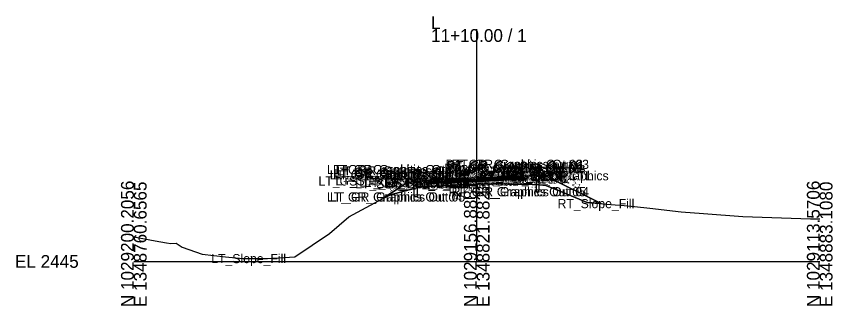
# Model space of a CAD drawing. Extents: x -26 to 1453, y -10 to 4527.
# Drawn here: x 1274.3 to 1452.8, y 490.3 to 553.7 of the extents above; entities that cross this region are included whole.
import ezdxf

# ---------------------------------------------------------------- set-up
doc = ezdxf.new("R2010")
doc.units = 0
for name, color, linetype in [('Default', 7, 'Continuous'), ('Exist Cross Section Cell', 7, 'Continuous'), ('Exist XS Center Line Elevation Label', 7, 'Continuous'), ('Exist XS Ground Line', 7, 'Continuous'), ('Old_Level_63', 7, 'Continuous'), ('Prop CMT Guardrail Graphics', 7, 'Continuous'), ('Prop CMT Pvmt Course 1', 7, 'Continuous'), ('Prop CMT Pvmt Course 2', 7, 'Continuous'), ('Prop CMT Pvmt Course 3', 7, 'Continuous'), ('Prop CMT Pvmt Surface', 7, 'Continuous'), ('Prop CMT Pvmt Surface Overlay', 7, 'Continuous'), ('Prop CMT Pvmt Surface Shoulder', 7, 'Continuous'), ('Prop CMT Shld Paved Course 1', 7, 'Continuous'), ('Prop CMT Shld Paved Course 2', 7, 'Continuous'), ('Prop CMT Shld Paved Course 3', 7, 'Continuous'), ('Prop CMT Slope Grass', 7, 'Continuous'), ('Prop CMT Subgrade Earthwork', 7, 'Continuous'), ('Prop XS Earthwork Shape', 7, 'Continuous'), ('Prop XS EOT Tick Mark', 7, 'Continuous'), ('Prop XS SE Text', 7, 'Continuous'), ('Prop XS Side Slope Text', 7, 'Continuous')]:
    doc.layers.add(name, color=color, linetype=linetype)

msp = doc.modelspace()

# ---------------------------------------------------------------- linework, layer by layer
at = {"layer": 'Exist Cross Section Cell'}
for p, q in [((1375, 500), (1375, 550.87)), ((1300, 500), (1375, 500)), ((1375, 500), (1450, 500))]:
    msp.add_line(p, q, dxfattribs=at)
at = {"layer": 'Exist XS Ground Line'}
msp.add_lwpolyline([(1300, 505.37), (1304.69, 504.48), (1307.15, 504.08), (1308.11, 503.92), (1309.26, 503.98), (1310.55, 503.15), (1314.96, 501.58), (1320.06, 501), (1323.81, 500.63), (1329.25, 500.62), (1335.24, 500.97), (1342.79, 506.1), (1347.02, 509.73), (1353.64, 513.34), (1356.17, 514.56), (1362.42, 516.23), (1367.27, 516.58), (1372.19, 516.81), (1375, 516.91), (1376.28, 516.96), (1381.72, 516.93), (1385.7, 516.95), (1389.88, 516.69), (1392.14, 515.8), (1399.17, 512.92), (1404.35, 512.47), (1407.24, 512.25), (1409.51, 512.01), (1412.85, 511.66), (1419.69, 510.86), (1424.57, 510.48), (1433.18, 509.87), (1447.99, 509.35), (1450, 509.29)], dxfattribs=at)
at = {"layer": 'Prop CMT Guardrail Graphics'}
for points in [[(1361.33, 514.12), (1361.33, 520.12)], [(1361.33, 520.12), (1362.66, 520.12), (1362.93, 519.83)], [(1362.93, 519.83), (1362.66, 519.53)], [(1362.66, 519.53), (1362.93, 519.24)], [(1388.66, 521.26), (1387.32, 521.26), (1387.05, 520.97)], [(1387.05, 520.97), (1387.32, 520.68)], [(1387.32, 520.68), (1387.05, 520.39)], [(1387.05, 520.39), (1387.32, 520.1), (1387.99, 520.1)], [(1387.99, 520.1), (1387.99, 515.26)], [(1388.66, 515.26), (1388.66, 521.26)], [(1362.93, 519.24), (1362.66, 518.95), (1361.99, 518.95)], [(1361.99, 518.95), (1361.99, 514.12)], [(1387.99, 515.26), (1388.66, 515.26)], [(1361.99, 514.12), (1361.33, 514.12)]]:
    msp.add_lwpolyline(points, dxfattribs=at)
at = {"layer": 'Prop CMT Pvmt Course 1'}
for points in [[(1375, 518.28), (1365, 517.78)], [(1365, 517.53), (1375, 518.03)], [(1365, 517.78), (1365, 517.53)], [(1375, 518.28), (1385, 518.78)], [(1385, 518.53), (1375, 518.03)], [(1375, 518.16), (1375, 518.28)], [(1375, 518.16), (1375, 518.28)], [(1375, 518.03), (1375, 518.16), (1375, 518.16)], [(1375, 518.03), (1375, 518.16), (1375, 518.16)], [(1385, 518.78), (1385, 518.53)]]:
    msp.add_lwpolyline(points, dxfattribs=at)
at = {"layer": 'Prop CMT Pvmt Course 2'}
for points in [[(1375, 518.03), (1365, 517.53)], [(1365, 517.28), (1375, 517.78)], [(1375, 518.03), (1385, 518.53)], [(1385, 518.28), (1375, 517.78)], [(1375, 517.78), (1375, 518.03)], [(1375, 517.78), (1375, 518.03)], [(1385, 518.53), (1385, 518.28)], [(1365, 517.53), (1365, 517.28)]]:
    msp.add_lwpolyline(points, dxfattribs=at)
at = {"layer": 'Prop CMT Pvmt Course 3'}
for points in [[(1375, 517.78), (1365, 517.28)], [(1375, 517.78), (1385, 518.28)], [(1385, 518.03), (1375, 517.53)], [(1375, 517.53), (1375, 517.78)], [(1375, 517.53), (1375, 517.78)], [(1385, 518.28), (1385, 518.03)], [(1365, 517.03), (1375, 517.53)], [(1365, 517.28), (1365, 517.03)]]:
    msp.add_lwpolyline(points, dxfattribs=at)
at = {"layer": 'Prop CMT Pvmt Surface'}
for points in [[(1375, 518.28), (1365, 517.78)], [(1375, 518.28), (1385, 518.78)]]:
    msp.add_lwpolyline(points, dxfattribs=at)
at = {"layer": 'Prop CMT Pvmt Surface Overlay'}
for points in [[(1375, 518.28), (1365, 517.78)], [(1375, 518.28), (1385, 518.78)]]:
    msp.add_lwpolyline(points, dxfattribs=at)
at = {"layer": 'Prop CMT Pvmt Surface Shoulder'}
for points in [[(1365, 517.78), (1365, 517.78)], [(1385, 518.78), (1385, 518.78)]]:
    msp.add_lwpolyline(points, dxfattribs=at)
at = {"layer": 'Prop CMT Shld Paved Course 1'}
for points in [[(1365, 517.78), (1365, 517.78), (1364.74, 517.52)], [(1365, 517.53), (1365, 517.78)], [(1385, 518.78), (1385, 518.78), (1385.24, 518.54)], [(1385, 518.53), (1385, 518.78)], [(1385.24, 518.54), (1385, 518.53)], [(1364.74, 517.52), (1365, 517.53)]]:
    msp.add_lwpolyline(points, dxfattribs=at)
at = {"layer": 'Prop CMT Shld Paved Course 2'}
for points in [[(1385, 518.53), (1385.24, 518.54), (1385.48, 518.31)], [(1385, 518.28), (1385, 518.53)], [(1385.48, 518.31), (1385, 518.28)], [(1365, 517.53), (1364.74, 517.52), (1364.47, 517.26)], [(1364.47, 517.26), (1365, 517.28)], [(1365, 517.28), (1365, 517.53)]]:
    msp.add_lwpolyline(points, dxfattribs=at)
at = {"layer": 'Prop CMT Shld Paved Course 3'}
for points in [[(1385, 518.28), (1385.48, 518.31)], [(1385, 518.03), (1385, 518.28)], [(1385.72, 518.07), (1385, 518.03)], [(1385.48, 518.31), (1385.48, 518.31)], [(1385.48, 518.31), (1385.72, 518.07)], [(1364.47, 517.26), (1364.21, 516.99)], [(1364.21, 516.99), (1365, 517.03)], [(1365, 517.28), (1364.47, 517.26)], [(1364.47, 517.26), (1364.47, 517.26)], [(1365, 517.03), (1365, 517.28)]]:
    msp.add_lwpolyline(points, dxfattribs=at)
at = {"layer": 'Prop CMT Slope Grass'}
for points in [[(1365, 517.78), (1362.93, 517.62)], [(1385, 518.78), (1387.05, 518.76)], [(1387.05, 518.76), (1390.05, 518.73)], [(1390.05, 518.73), (1402.2, 512.66)], [(1359.93, 517.38), (1354.49, 513.75)], [(1362.93, 517.62), (1359.93, 517.38)]]:
    msp.add_lwpolyline(points, dxfattribs=at)
at = {"layer": 'Prop CMT Subgrade Earthwork'}
for points in [[(1375, 517.53), (1385, 518.03)], [(1385, 518.03), (1385.72, 518.07)], [(1385.72, 518.07), (1386.42, 518.77)], [(1364.21, 516.99), (1363.54, 517.67)], [(1365, 517.03), (1364.21, 516.99)], [(1375, 517.53), (1365, 517.03)]]:
    msp.add_lwpolyline(points, dxfattribs=at)
at = {"layer": 'Prop XS Earthwork Shape'}
for points in [[(1390.05, 518.73), (1402.2, 512.66), (1399.17, 512.92), (1392.14, 515.8), (1389.88, 516.69), (1385.7, 516.95), (1381.72, 516.93), (1376.28, 516.96), (1375, 516.91), (1372.19, 516.81), (1367.27, 516.58), (1362.42, 516.23), (1356.17, 514.56), (1354.49, 513.75), (1359.93, 517.38), (1362.93, 517.62), (1363.54, 517.67), (1364.21, 516.99), (1365, 517.03), (1375, 517.53), (1385, 518.03), (1385.72, 518.07), (1386.42, 518.77), (1387.05, 518.76)], [(1365, 517.03), (1364.21, 516.99), (1363.54, 517.67), (1362.93, 517.62), (1359.93, 517.38), (1354.49, 513.75), (1356.17, 514.56), (1362.42, 516.23), (1367.27, 516.58), (1372.19, 516.81), (1375, 516.91), (1376.28, 516.96), (1381.72, 516.93), (1385.7, 516.95), (1389.88, 516.69), (1392.14, 515.8), (1399.17, 512.92), (1402.2, 512.66), (1390.05, 518.73), (1387.05, 518.76), (1386.42, 518.77), (1385.72, 518.07), (1385, 518.03), (1375, 517.53)]]:
    msp.add_lwpolyline(points, close=True, dxfattribs=at)
at = {"layer": 'Prop XS EOT Tick Mark'}
for points in [[(1385, 518.78), (1385, 519.78)], [(1365, 517.78), (1365, 518.78)]]:
    msp.add_lwpolyline(points, dxfattribs=at)

# ---------------------------------------------------------------- texts
at = {"layer": 'Default'}
msp.add_text('-', height=0.0001, dxfattribs=at).set_placement((1300, 500))
at = {"layer": 'Exist Cross Section Cell'}
for s, p in [('L', (1365, 550.87)), ('11+10.00 / 1', (1365, 548.07)), ('EL 2445', (1274, 498.6))]:
    msp.add_text(s, height=2.8, dxfattribs=at).set_placement(p)
for s, p in [('N 1029200.2056', (1300, 490)), ('E 1348760.6565', (1302.8, 490)), ('N 1029156.8881', (1375, 490)), ('E 1348821.8823', (1377.8, 490)), ('N 1029113.5706', (1450, 490)), ('E 1348883.1080', (1452.8, 490))]:
    msp.add_text(s, height=2.8, rotation=90, dxfattribs=at).set_placement(p)
at = {"layer": 'Exist XS Center Line Elevation Label'}
msp.add_text('2461.91', height=1.23, dxfattribs=at).set_placement((1372.25, 515.18))
at = {"layer": 'Old_Level_63'}
for s, p in [('RT_GR_Graphics Out 08', (1367.9, 519.39)), ('RT_GR_Graphics Out 02', (1368.17, 520.26)), ('RT_GR_Graphics Out 09', (1368.17, 519.68)), ('RT_GR_Graphics Out 01', (1368.47, 519.97)), ('RT_GR_Graphics Out 03', (1369.51, 520.26)), ('LT_GR_Graphics Out 03', (1342.22, 519.12)), ('LT_GR_Graphics Out 06', (1342.84, 517.95)), ('LT_GR_Graphics Out 02', (1343.56, 519.12)), ('LT_GR_Graphics Out 09', (1343.56, 518.53)), ('LT_GR_Graphics Out 07', (1343.56, 517.95)), ('LT_GR_Graphics Out 08', (1343.83, 518.24)), ('LT_GR_Graphics Out 01', (1344.4, 518.83)), ('LT_TM_OEOT', (1355.94, 517.78)), ('RT_GS_OS_GR_Face_Graphics', (1364.46, 517.76)), ('RT_Sub_Trench_Out_DLT', (1366.94, 517.77)), ('RT_GR_Graphics Out 07', (1368.17, 519.1)), ('RT_GR_Graphics Out 06', (1368.79, 519.1)), ('RT_PV2_OEOT', (1375.13, 517.53)), ('RT_PS2_OEOP', (1375.43, 517.54)), ('RT_PV1_OEOT', (1375.69, 517.78)), ('RT_PS1_OEOP', (1375.76, 517.78)), ('RT_TM_OEOT', (1375.9, 518.78)), ('RT_GS_OS_CTL', (1379.38, 517.73)), ('LT_GS_OS_GR_Face_Graphics', (1340.39, 516.62)), ('LT_Sub_Trench_Out_DLT', (1344.1, 516.67)), ('LT_Sub_Trench_Out', (1348.41, 515.99)), ('LT_GS_OS_CTL', (1349.3, 516.38)), ('LT_PS3_Shelf_Out', (1350.46, 516.26)), ('LT_PS3_OEOP', (1354.71, 516.26)), ('LT_PS2_OEOP', (1354.97, 516.52)), ('LT_Sub_OEOT', (1355.08, 516.03)), ('LT_PV2_OEOT', (1355.17, 516.53)), ('LT_PV3_OEOT', (1355.17, 516.28)), ('LT_PV1_OEOT', (1355.74, 516.78)), ('LT_PS1_OEOP', (1355.8, 516.78)), ('RT_PV1_OEEOP_W', (1362.94, 517.16)), ('LT_PV1_OEEOP_W', (1362.98, 517.16)), ('RT_Sub_OEEOP', (1364.17, 516.53)), ('LT_Sub_OEEOP', (1364.21, 516.53)), ('RT_PV2_OEEOP', (1364.26, 517.03)), ('RT_PV3_OEEOP', (1364.26, 516.78)), ('LT_PV2_OEEOP', (1364.31, 517.03)), ('LT_PV3_OEEOP', (1364.31, 516.78)), ('PV1_PGL_W', (1367.58, 517.16)), ('PV1_PGL', (1369.47, 517.28)), ('RT_Sub_Trench_Out', (1369.87, 517.07)), ('RT_PS3_Shelf_Out', (1371.41, 517.31)), ('RT_Sub_OEOT', (1375.03, 517.03)), ('RT_PV3_OEOT', (1375.13, 517.28)), ('RT_PS3_OEOP', (1375.67, 517.31)), ('RT_GR_Graphics Out 05', (1368.84, 514.26)), ('RT_GR_Graphics Out 04', (1369.51, 514.26)), ('LT_GR_Graphics Out 04', (1342.22, 513.12)), ('LT_GR_Graphics Out 05', (1342.89, 513.12)), ('RT_Slope_Fill', (1392.67, 511.66)), ('LT_Slope_Fill', (1316.94, 499.62))]:
    msp.add_text(s, height=2, dxfattribs=at).set_placement(p)
at = {"layer": 'Prop XS SE Text'}
for p in [(1368.2, 518.94), (1378.2, 519.44)]:
    msp.add_text('0.050', height=1, rotation=2.8624, dxfattribs=at).set_placement(p)
at = {"layer": 'Prop XS Side Slope Text'}
for s, rotation, p in [('1.5:1', 33.6901, (1356.05, 515.17)), ('2:1', 333.4349, (1395.75, 516.72))]:
    msp.add_text(s, height=1, rotation=rotation, dxfattribs=at).set_placement(p)

doc.saveas('drawing.dxf')
